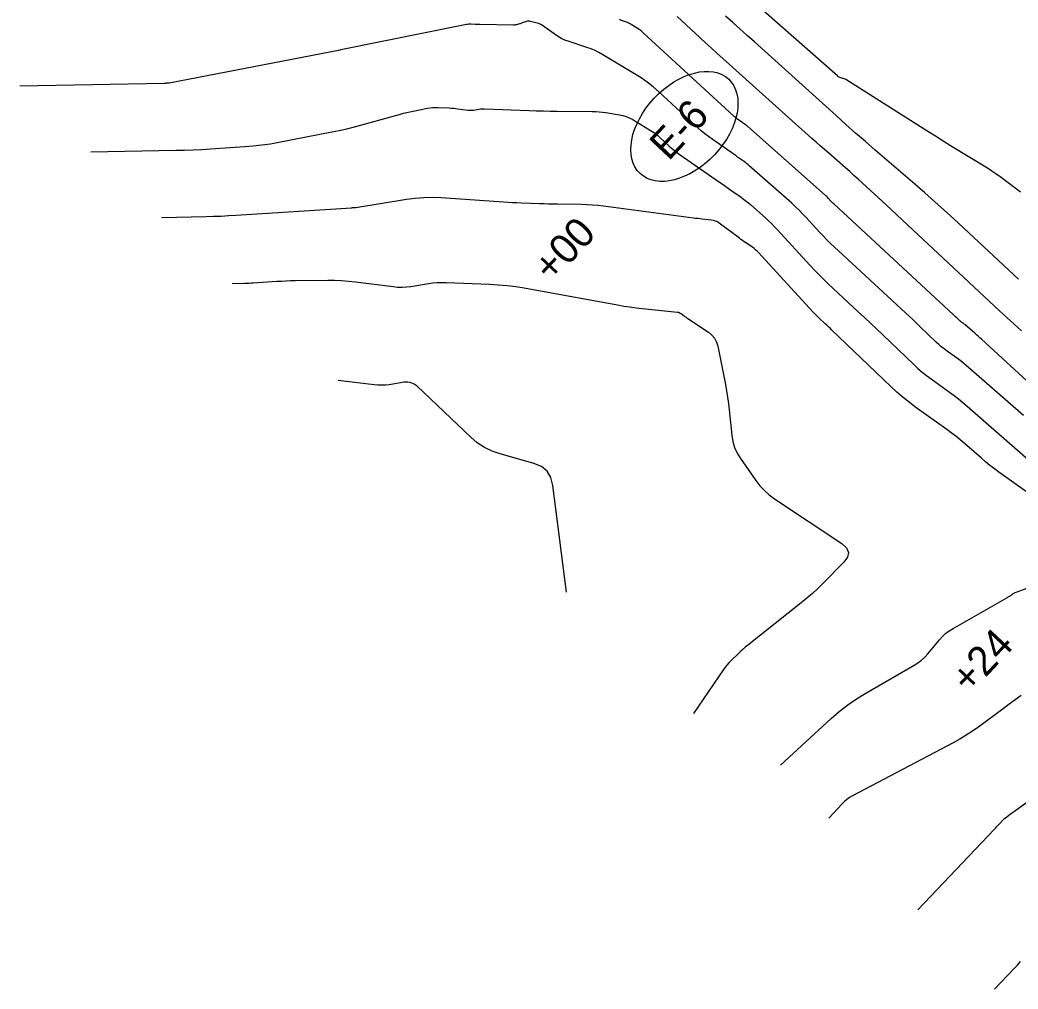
# Model space of a CAD drawing. Extents: x 1005228 to 1008882, y 1883389 to 1885754.
# Drawn here: x 1006804 to 1007015.2, y 1885263.1 to 1885468.1 of the extents above; entities that cross this region are included whole.
import ezdxf

# ---------------------------------------------------------------- set-up
doc = ezdxf.new("R2010")
doc.units = 0
for name, color, linetype in [('C-ANNO-NOTE', 7, 'Continuous'), ('R_Erosion', 7, 'Continuous'), ('S_BASELINE', 7, 'Continuous'), ('S_BRIDGE', 7, 'Continuous')]:
    doc.layers.add(name, color=color, linetype=linetype)

msp = doc.modelspace()

# ---------------------------------------------------------------- linework, layer by layer
at = {"layer": 'C-ANNO-NOTE'}
for points in [[(1007015.73, 1885431.7), (1007012.3, 1885434.3), (1007011.43, 1885434.94), (1007010.55, 1885435.56), (1007009.65, 1885436.15), (1007008.74, 1885436.73), (1007000.95, 1885441.51), (1006999.35, 1885442.5), (1006997.75, 1885443.5), (1006996.15, 1885444.49), (1006994.55, 1885445.5), (1006978.75, 1885455.49), (1006978.61, 1885455.57), (1006978.46, 1885455.65), (1006978.31, 1885455.71), (1006978.16, 1885455.76), (1006977.53, 1885455.95), (1006977.38, 1885456), (1006977.24, 1885456.07), (1006977.1, 1885456.16), (1006976.98, 1885456.26), (1006944.67, 1885484.8)], [(1007015.94, 1885402.31), (1007014.4, 1885403.74), (1007012.85, 1885405.17), (1007011.31, 1885406.6), (1006991.8, 1885424.78), (1006990.67, 1885425.83), (1006989.54, 1885426.87), (1006988.41, 1885427.92), (1006987.28, 1885428.97), (1006982.23, 1885433.64), (1006981.36, 1885434.44), (1006980.48, 1885435.24), (1006979.6, 1885436.02), (1006978.71, 1885436.8), (1006975.15, 1885439.91), (1006974.26, 1885440.69), (1006973.37, 1885441.47), (1006972.49, 1885442.26), (1006971.61, 1885443.04), (1006952.78, 1885459.93), (1006951.56, 1885461.04), (1006950.34, 1885462.15), (1006949.12, 1885463.26), (1006947.9, 1885464.38), (1006943.06, 1885468.85)], [(1007015.31, 1885413.24), (1007001.62, 1885426.01), (1006999.59, 1885427.88), (1006997.54, 1885429.74), (1006995.47, 1885431.57), (1006993.39, 1885433.38), (1006985.01, 1885440.57), (1006982.92, 1885442.38), (1006980.84, 1885444.19), (1006978.78, 1885446.02), (1006976.72, 1885447.87), (1006959.43, 1885463.47), (1006957.9, 1885464.85), (1006956.38, 1885466.22), (1006954.84, 1885467.58), (1006953.31, 1885468.94)], [(1007031.99, 1885378.09), (1007007.48, 1885400.56), (1007007.12, 1885400.88), (1007006.76, 1885401.21), (1007006.4, 1885401.53), (1007006.04, 1885401.85), (1007004.03, 1885403.6), (1007003.94, 1885403.68), (1007003.84, 1885403.76), (1007003.74, 1885403.84), (1007003.64, 1885403.91), (1007003.22, 1885404.21), (1007003.12, 1885404.28), (1007003.02, 1885404.36), (1007002.93, 1885404.45), (1007002.84, 1885404.53), (1007002.16, 1885405.18), (1007002.01, 1885405.32), (1007001.87, 1885405.46), (1007001.73, 1885405.59), (1007001.58, 1885405.73), (1006976.22, 1885429.2), (1006976.06, 1885429.34), (1006975.91, 1885429.49), (1006975.76, 1885429.65), (1006975.61, 1885429.8), (1006975.04, 1885430.43), (1006974.89, 1885430.59), (1006974.74, 1885430.74), (1006974.58, 1885430.89), (1006974.43, 1885431.03), (1006958.02, 1885445.59), (1006957.94, 1885445.66), (1006957.85, 1885445.73), (1006957.77, 1885445.8), (1006957.68, 1885445.86), (1006957.33, 1885446.1), (1006957.25, 1885446.16), (1006957.16, 1885446.23), (1006957.07, 1885446.29), (1006956.99, 1885446.35), (1006955.84, 1885447.15), (1006955.62, 1885447.3), (1006955.41, 1885447.47), (1006955.2, 1885447.64), (1006955, 1885447.82), (1006935.89, 1885465.42), (1006935.59, 1885465.68), (1006935.28, 1885465.92), (1006934.96, 1885466.15), (1006934.62, 1885466.36), (1006932.98, 1885467.35), (1006932.78, 1885467.46), (1006932.57, 1885467.56), (1006932.36, 1885467.65), (1006932.15, 1885467.73), (1006931.28, 1885468.01), (1006931.07, 1885468.09), (1006930.86, 1885468.18)], [(1006819, 1885440.18), (1006837.04, 1885440.54), (1006838.86, 1885440.59), (1006840.68, 1885440.65), (1006842.5, 1885440.74), (1006844.32, 1885440.85), (1006851.59, 1885441.33), (1006853.41, 1885441.48), (1006855.21, 1885441.68), (1006857.01, 1885441.94), (1006858.81, 1885442.26), (1006869.99, 1885444.41), (1006871.6, 1885444.74), (1006873.2, 1885445.1), (1006874.79, 1885445.49), (1006876.38, 1885445.91), (1006884.52, 1885448.18), (1006885.19, 1885448.36), (1006885.87, 1885448.53), (1006886.55, 1885448.68), (1006887.24, 1885448.83), (1006890.26, 1885449.44), (1006890.81, 1885449.53), (1006891.36, 1885449.59), (1006891.91, 1885449.62), (1006892.46, 1885449.61), (1006894.87, 1885449.5), (1006895.33, 1885449.48), (1006895.78, 1885449.44), (1006896.24, 1885449.4), (1006896.69, 1885449.34), (1006898.83, 1885449.04), (1006899.12, 1885449.01), (1006899.41, 1885449), (1006899.7, 1885449.02), (1006899.99, 1885449.06), (1006901.16, 1885449.25), (1006901.45, 1885449.29), (1006901.75, 1885449.32), (1006902.04, 1885449.33), (1006902.33, 1885449.33), (1006911.77, 1885448.97), (1006913.25, 1885448.92), (1006914.73, 1885448.88), (1006916.21, 1885448.85), (1006917.7, 1885448.83), (1006925.14, 1885448.74), (1006925.87, 1885448.72), (1006926.59, 1885448.67), (1006927.31, 1885448.6), (1006928.03, 1885448.5), (1006930.89, 1885448.06), (1006931.59, 1885447.92), (1006932.28, 1885447.71), (1006932.93, 1885447.43), (1006933.57, 1885447.1), (1006937.25, 1885444.89), (1006937.82, 1885444.53), (1006938.38, 1885444.14), (1006938.91, 1885443.72), (1006939.42, 1885443.27), (1006941.41, 1885441.43), (1006941.92, 1885440.98), (1006942.44, 1885440.55), (1006942.98, 1885440.13), (1006943.53, 1885439.74), (1006952.28, 1885433.64), (1006952.83, 1885433.27), (1006953.37, 1885432.89), (1006953.91, 1885432.51), (1006954.45, 1885432.13), (1006956.62, 1885430.6), (1006957.15, 1885430.22), (1006957.68, 1885429.81), (1006958.19, 1885429.4), (1006958.69, 1885428.97), (1006961.75, 1885426.25), (1006962.42, 1885425.64), (1006963.07, 1885425.02), (1006963.71, 1885424.38), (1006964.32, 1885423.72), (1006971.17, 1885416.26), (1006972.39, 1885414.97), (1006973.63, 1885413.69), (1006974.9, 1885412.45), (1006976.19, 1885411.22), (1006981.42, 1885406.39), (1006982.72, 1885405.17), (1006984.02, 1885403.96), (1006985.31, 1885402.73), (1006986.6, 1885401.5), (1006993.15, 1885395.21), (1006994.03, 1885394.4), (1006994.93, 1885393.62), (1006995.86, 1885392.88), (1006996.82, 1885392.16), (1007000.71, 1885389.37), (1007001.68, 1885388.66), (1007002.62, 1885387.93), (1007003.55, 1885387.18), (1007004.46, 1885386.41), (1007018.52, 1885374.14)], [(1007017.03, 1885368.31), (1007011.18, 1885372.45), (1007010.22, 1885373.15), (1007009.28, 1885373.87), (1007008.35, 1885374.62), (1007007.45, 1885375.39), (1007003.86, 1885378.52), (1007002.95, 1885379.29), (1007002.03, 1885380.04), (1007001.09, 1885380.77), (1007000.13, 1885381.47), (1006993.62, 1885386.14), (1006992.23, 1885387.17), (1006990.88, 1885388.25), (1006989.57, 1885389.38), (1006988.31, 1885390.56), (1006975.77, 1885402.59), (1006975.44, 1885402.9), (1006975.11, 1885403.22), (1006974.77, 1885403.53), (1006974.44, 1885403.85), (1006973.09, 1885405.09), (1006972.76, 1885405.41), (1006972.43, 1885405.73), (1006972.11, 1885406.06), (1006971.8, 1885406.39), (1006960.28, 1885418.93), (1006959.99, 1885419.23), (1006959.68, 1885419.51), (1006959.35, 1885419.77), (1006959.01, 1885420.02), (1006957.62, 1885420.95), (1006957.27, 1885421.18), (1006956.93, 1885421.42), (1006956.58, 1885421.67), (1006956.25, 1885421.92), (1006951.99, 1885425.11), (1006951.6, 1885425.37), (1006951.19, 1885425.57), (1006950.75, 1885425.7), (1006950.29, 1885425.78), (1006948.41, 1885425.98), (1006947.94, 1885426.03), (1006947.47, 1885426.08), (1006947, 1885426.14), (1006946.53, 1885426.2), (1006927.48, 1885428.73), (1006926.33, 1885428.86), (1006925.18, 1885428.96), (1006924.02, 1885429.03), (1006922.86, 1885429.06), (1006917.8, 1885429.12), (1006916.85, 1885429.13), (1006915.89, 1885429.15), (1006914.94, 1885429.18), (1006913.98, 1885429.21), (1006910.16, 1885429.36), (1006909.2, 1885429.4), (1006908.25, 1885429.44), (1006907.29, 1885429.5), (1006906.34, 1885429.56), (1006893.12, 1885430.47), (1006891.29, 1885430.54), (1006889.47, 1885430.51), (1006887.65, 1885430.37), (1006885.83, 1885430.13), (1006875.12, 1885428.38), (1006875.04, 1885428.37), (1006874.96, 1885428.36), (1006874.88, 1885428.35), (1006874.8, 1885428.35), (1006874.48, 1885428.35), (1006874.39, 1885428.34), (1006874.31, 1885428.34), (1006874.23, 1885428.34), (1006874.15, 1885428.33), (1006849.74, 1885426.73), (1006848.16, 1885426.64), (1006846.59, 1885426.56), (1006845.01, 1885426.5), (1006843.43, 1885426.46), (1006833.97, 1885426.28)], [(1006848.94, 1885412.37), (1006851.61, 1885412.42), (1006852.05, 1885412.43), (1006852.5, 1885412.45), (1006852.94, 1885412.47), (1006853.39, 1885412.5), (1006858.36, 1885412.82), (1006859.34, 1885412.88), (1006860.31, 1885412.93), (1006861.29, 1885412.96), (1006862.27, 1885412.97), (1006869.15, 1885413.05), (1006870.62, 1885413.04), (1006872.09, 1885412.98), (1006873.55, 1885412.87), (1006875.02, 1885412.71), (1006883.01, 1885411.69), (1006883.95, 1885411.6), (1006884.88, 1885411.59), (1006885.81, 1885411.63), (1006886.74, 1885411.75), (1006890.45, 1885412.34), (1006891.38, 1885412.47), (1006892.32, 1885412.55), (1006893.25, 1885412.58), (1006894.19, 1885412.57), (1006903.41, 1885412.21), (1006905.25, 1885412.11), (1006907.09, 1885411.94), (1006908.93, 1885411.71), (1006910.75, 1885411.41), (1006930.5, 1885407.81), (1006931.8, 1885407.59), (1006933.1, 1885407.39), (1006934.4, 1885407.21), (1006935.71, 1885407.07), (1006943.13, 1885406.3), (1006943.34, 1885406.26), (1006943.54, 1885406.2), (1006943.73, 1885406.11), (1006943.91, 1885405.99), (1006944.61, 1885405.47), (1006944.78, 1885405.34), (1006944.96, 1885405.22), (1006945.14, 1885405.09), (1006945.32, 1885404.97), (1006949.74, 1885402.03), (1006950.46, 1885401.45), (1006951.02, 1885400.76), (1006951.44, 1885399.98), (1006951.7, 1885399.09), (1006953.3, 1885390.98), (1006953.55, 1885389.65), (1006953.76, 1885388.32), (1006953.95, 1885386.98), (1006954.1, 1885385.63), (1006954.65, 1885380.25), (1006954.87, 1885378.93), (1006955.25, 1885377.68), (1006955.78, 1885376.48), (1006956.48, 1885375.34), (1006959.75, 1885370.66), (1006960.6, 1885369.56), (1006961.54, 1885368.55), (1006962.57, 1885367.63), (1006963.69, 1885366.8), (1006977.93, 1885357.32), (1006978.92, 1885356.42), (1006979.32, 1885355.47), (1006979.12, 1885354.45), (1006978.33, 1885353.38), (1006973.96, 1885348.95), (1006972.86, 1885347.86), (1006971.72, 1885346.81), (1006970.55, 1885345.79), (1006969.35, 1885344.8), (1006957.97, 1885335.77), (1006957.5, 1885335.39), (1006957.04, 1885335), (1006956.59, 1885334.6), (1006956.15, 1885334.18), (1006954.42, 1885332.51), (1006953.99, 1885332.08), (1006953.6, 1885331.63), (1006953.22, 1885331.17), (1006952.87, 1885330.68), (1006946.56, 1885321.4)], [(1006919.69, 1885347.05), (1006916.81, 1885369.63), (1006916.39, 1885371.3), (1006915.57, 1885372.64), (1006914.37, 1885373.64), (1006912.78, 1885374.3), (1006905.65, 1885376.3), (1006903.92, 1885376.89), (1006902.31, 1885377.68), (1006900.8, 1885378.66), (1006899.4, 1885379.84), (1006888.05, 1885390.61), (1006887.45, 1885391.08), (1006886.79, 1885391.37), (1006886.08, 1885391.5), (1006885.31, 1885391.46), (1006882.15, 1885390.95), (1006881.36, 1885390.86), (1006880.57, 1885390.82), (1006879.77, 1885390.83), (1006878.98, 1885390.9), (1006871.35, 1885391.87)], [(1006964.96, 1885310.49), (1006975.67, 1885320.33), (1006977.39, 1885321.83), (1006979.19, 1885323.22), (1006981.06, 1885324.52), (1006983, 1885325.71), (1006993.22, 1885331.61), (1006994.02, 1885332.12), (1006994.77, 1885332.69), (1006995.47, 1885333.33), (1006996.11, 1885334.03), (1006998.57, 1885336.96), (1006999.21, 1885337.67), (1006999.9, 1885338.3), (1007000.65, 1885338.87), (1007001.46, 1885339.38), (1007012.85, 1885345.86), (1007013, 1885345.95), (1007013.15, 1885346.05), (1007013.29, 1885346.14), (1007013.44, 1885346.24), (1007014.01, 1885346.65), (1007014.15, 1885346.74), (1007014.3, 1885346.83), (1007014.46, 1885346.91), (1007014.62, 1885346.97), (1007017.33, 1885347.99)], [(1007015.87, 1885325.19), (1007014.6, 1885324.27), (1007013.33, 1885323.34), (1007012.07, 1885322.41), (1007006.9, 1885318.57), (1007005.6, 1885317.64), (1007004.27, 1885316.77), (1007002.91, 1885315.95), (1007001.51, 1885315.18), (1006980.17, 1885303.95), (1006979.58, 1885303.6), (1006979.02, 1885303.21), (1006978.49, 1885302.77), (1006978, 1885302.29), (1006975.16, 1885299.26)], [(1007010.26, 1885263.1), (1007014.39, 1885267.44), (1007015.08, 1885268.17), (1007015.76, 1885268.89)]]:
    msp.add_lwpolyline(points, dxfattribs=at)
at = {"layer": 'R_Erosion'}
msp.add_ellipse((1006944.62, 1885445.59), major_axis=(9.37, 9.99), ratio=0.638788, dxfattribs=at)
at = {"layer": 'S_BRIDGE'}
for points in [[(1007016.39, 1885384.41), (1007004.25, 1885395), (1007003.74, 1885395.43), (1007003.23, 1885395.85), (1007002.71, 1885396.25), (1007002.17, 1885396.64), (1007000.02, 1885398.19), (1006999.49, 1885398.58), (1006998.98, 1885398.99), (1006998.48, 1885399.42), (1006997.99, 1885399.87), (1006994.45, 1885403.27), (1006993.7, 1885403.99), (1006992.95, 1885404.71), (1006992.19, 1885405.42), (1006991.43, 1885406.12), (1006976.32, 1885420.1), (1006975.54, 1885420.84), (1006974.77, 1885421.6), (1006974.02, 1885422.36), (1006973.29, 1885423.15), (1006970.38, 1885426.32), (1006969.64, 1885427.1), (1006968.89, 1885427.86), (1006968.11, 1885428.6), (1006967.32, 1885429.33), (1006958.35, 1885437.28), (1006958.06, 1885437.53), (1006957.76, 1885437.77), (1006957.46, 1885438.01), (1006957.15, 1885438.23), (1006955.89, 1885439.11), (1006955.58, 1885439.34), (1006955.26, 1885439.56), (1006954.95, 1885439.78), (1006954.63, 1885440), (1006950.49, 1885442.88), (1006949.71, 1885443.44), (1006948.95, 1885444.03), (1006948.2, 1885444.65), (1006947.48, 1885445.29), (1006939.24, 1885452.88), (1006938.03, 1885453.95), (1006936.76, 1885454.94), (1006935.45, 1885455.87), (1006934.09, 1885456.73), (1006927.36, 1885460.76), (1006926.55, 1885461.21), (1006925.72, 1885461.62), (1006924.87, 1885461.98), (1006923.99, 1885462.29), (1006920, 1885463.6), (1006919.35, 1885463.84), (1006918.72, 1885464.12), (1006918.11, 1885464.46), (1006917.53, 1885464.84), (1006914.62, 1885466.91), (1006914.36, 1885467.08), (1006914.08, 1885467.22), (1006913.79, 1885467.34), (1006913.49, 1885467.44), (1006912.07, 1885467.81), (1006911.86, 1885467.85), (1006911.65, 1885467.86), (1006911.45, 1885467.83), (1006911.24, 1885467.78), (1006910.32, 1885467.47), (1006910.16, 1885467.42), (1006910.01, 1885467.37), (1006909.85, 1885467.32), (1006909.7, 1885467.27), (1006909.08, 1885467.09), (1006908.92, 1885467.05), (1006908.77, 1885467.02), (1006908.61, 1885467), (1006908.45, 1885467), (1006901.31, 1885467.14), (1006901.08, 1885467.15), (1006900.84, 1885467.16), (1006900.61, 1885467.16), (1006900.38, 1885467.17), (1006899.44, 1885467.21), (1006899.21, 1885467.22), (1006898.98, 1885467.21), (1006898.74, 1885467.18), (1006898.51, 1885467.14), (1006871.9, 1885461.78), (1006871.89, 1885461.77), (1006871.88, 1885461.77), (1006871.87, 1885461.77), (1006871.86, 1885461.77), (1006871.81, 1885461.75), (1006871.8, 1885461.75), (1006871.79, 1885461.75), (1006871.78, 1885461.74), (1006871.77, 1885461.74), (1006835.59, 1885454.77), (1006835.51, 1885454.76), (1006835.43, 1885454.75), (1006835.35, 1885454.74), (1006835.27, 1885454.73), (1006834.94, 1885454.71), (1006834.85, 1885454.7), (1006834.77, 1885454.7), (1006834.69, 1885454.7), (1006834.61, 1885454.7), (1006804.03, 1885454.09)], [(1006993.99, 1885279.86), (1007010.21, 1885296.93), (1007010.43, 1885297.16), (1007010.64, 1885297.38), (1007010.86, 1885297.61), (1007011.07, 1885297.84), (1007012.33, 1885299.18), (1007012.34, 1885299.19), (1007012.35, 1885299.2), (1007012.37, 1885299.21), (1007012.38, 1885299.22), (1007012.44, 1885299.25), (1007012.45, 1885299.26), (1007012.46, 1885299.26), (1007012.48, 1885299.27), (1007012.49, 1885299.28), (1007013.65, 1885300.14), (1007013.84, 1885300.29), (1007014.04, 1885300.43), (1007014.24, 1885300.58), (1007014.44, 1885300.72), (1007034.6, 1885315.4)]]:
    msp.add_lwpolyline(points, dxfattribs=at)

# ---------------------------------------------------------------- texts
at = {"layer": 'R_Erosion'}
msp.add_text('E-6', height=6.25, rotation=46.8499, dxfattribs=at).set_placement((1006941.26, 1885438.11))
at = {"layer": 'S_BASELINE'}
for s, p in [('+00', (1006916.53, 1885412.34)), ('+24', (1007004.93, 1885325.29))]:
    msp.add_text(s, height=6.25, rotation=46.8499, dxfattribs=at).set_placement(p)

doc.saveas('drawing.dxf')
